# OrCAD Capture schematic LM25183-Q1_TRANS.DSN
size E; title: LM25183-Q1 42-VIN PSR Flyback DC/DC Converter with 65-V,; rev: 1.0; note: Datasheet: SNVSBJ4    EVM: NA; note: Synchronous Step Down Converter
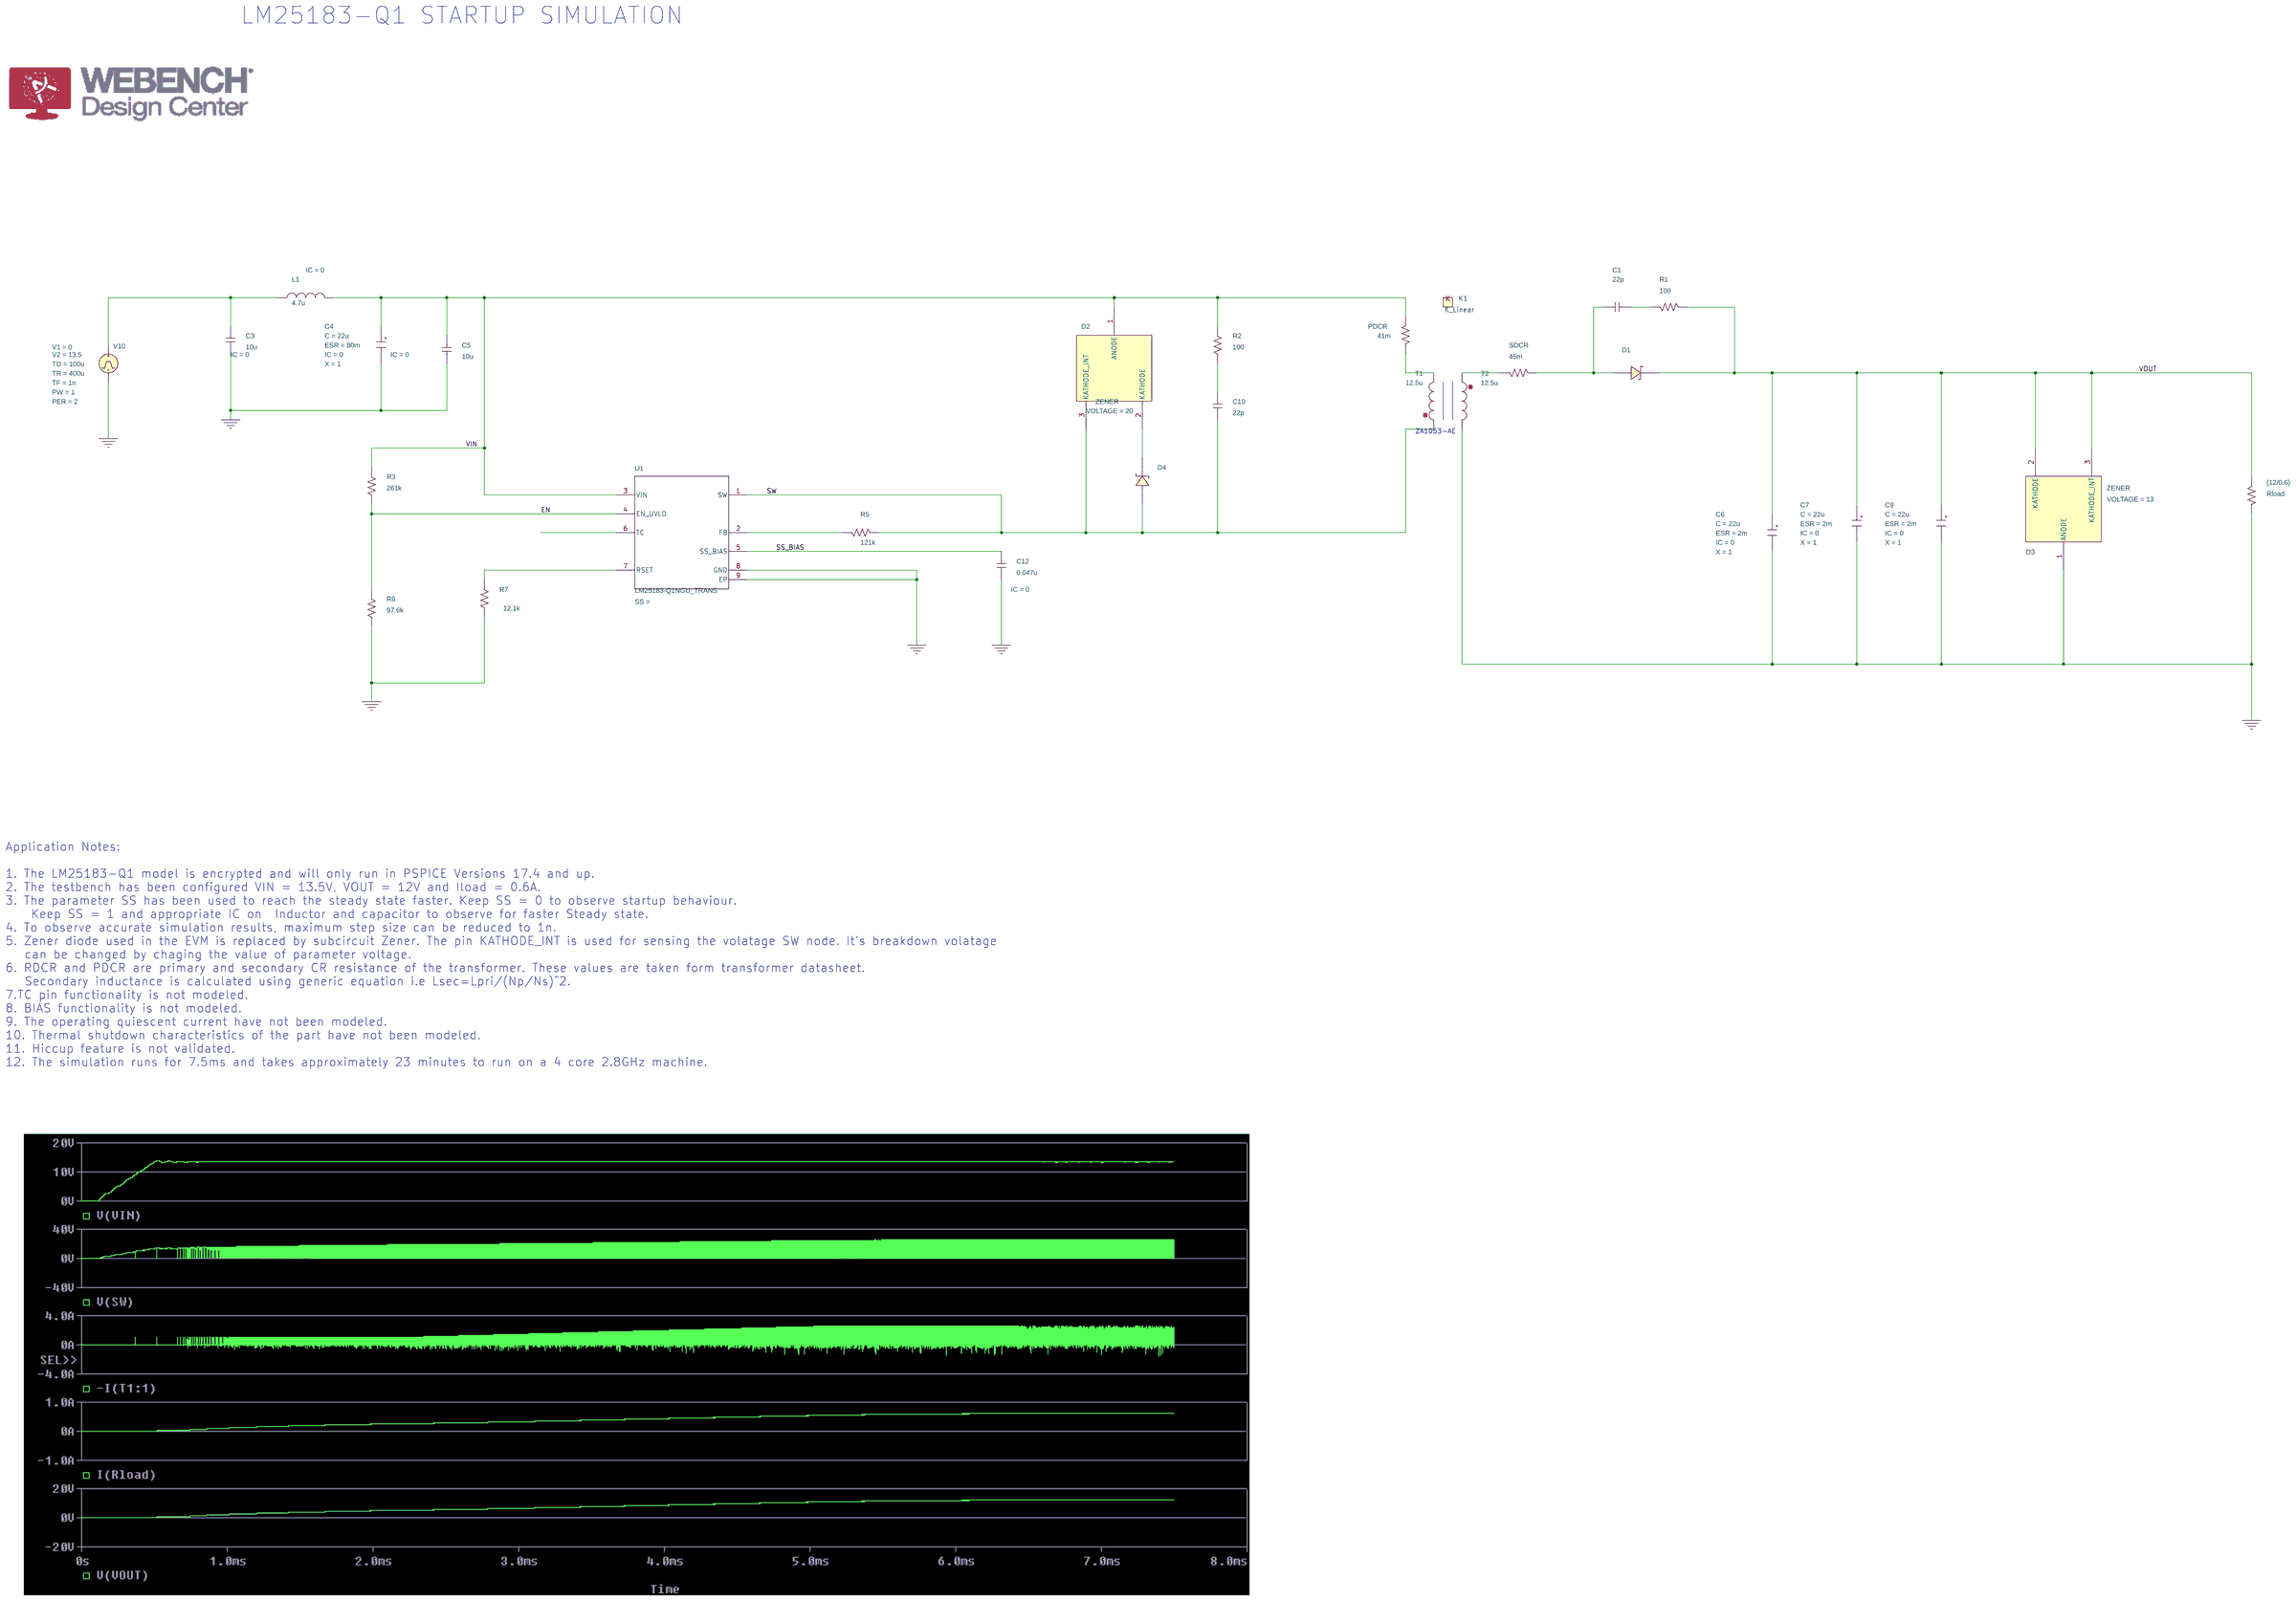
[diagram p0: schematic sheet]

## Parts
C1  22p  [RAD/CK05]
C3  10u  [RAD/CK05]
C4  CESR
C5  10u  [RAD/CK05]
C6  CESR
C7  CESR
C9  CESR
C10  22p  [RAD/CK05]
C12  0.047u  [RAD/CK05]
D1  D_D
D2  ZENER
D3  ZENER
D4  D_D
K1  K_Linear
L1  4.7u  [DISC/.350x.175/LS.200x.100/.034]
PDCR  41m  [AX/RC05]
R1  100  [AX/RC05]
R2  100  [AX/RC05]
R3  261k  [AX/RC05]
R5  121k  [AX/RC05]
R6  97.6k  [AX/RC05]
R7  12.1k  [AX/RC05]
Rload  {12/0.6}  [AX/RC05]
SDCR  45m  [AX/RC05]
T1  12.5u  [DISC/.350x.175/LS.200x.100/.034]
T2  12.5u  [DISC/.350x.175/LS.200x.100/.034]
U1  LM25183-Q1NGU_TRANS  [NGU0008C-IPC_A]
V10  VPULSE

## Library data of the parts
C1 C10 = C
C3 C5 C12 = C: IC: 0
C4 = CESR_0: C: 22u; ESR: 80m; IC: 0; PSpiceTemplate: X^@REFDES %IN %OUT @MODEL PARAMS:  ?C|C=@C||C=100u|  ?ESR|ESR=@ESR||ESR=0.01| ?X|X=@X||X=2|  ?IC|IC=@IC||IC=2|; X: 1
C6 C7 C9 = CESR_0: C: 22u; ESR: 2m; IC: 0; PSpiceTemplate: X^@REFDES %IN %OUT @MODEL PARAMS:  ?C|C=@C||C=100u|  ?ESR|ESR=@ESR||ESR=0.01| ?X|X=@X||X=2|  ?IC|IC=@IC||IC=2|; X: 1
D1 = D_D_2_1: PSpiceTemplate: D^@REFDES %1 %2 @MODEL
D2 = ZENER: VOLTAGE: 20
D3 = ZENER: VOLTAGE: 13
D4 = D_D_2: PSpiceTemplate: D^@REFDES %1 %2 @MODEL
K1 = K_Linear: COUPLING: 1; L1: T1; L2: T2
L1 = L_v2: IC: 0
PDCR R1-R3 R5-R7 Rload SDCR = R
T1 T2 = L
U1 = LM25183-Q1NGU_TRANS
V10 = VPULSE: PER: 2; PW: 1; TD: 100u; TF: 1n; TR: 400u; V1: 0; V2: 13.5

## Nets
VIN: C4.1(IN) C5.1 D2.1(ANODE) L1.2 PDCR.2 R2.1 R3.1 U1.3(VIN)
0: C3.2 C4.3(OUT) C5.2 C6.3(OUT) C7.3(OUT) C9.3(OUT) C12.2 D3.1(ANODE) R6.2 R7.2 Rload.2 T2.2 U1.8(GND) U1.9(EP) V10.2(-)
EN: R3.2 R6.1 U1.4(EN_UVLO)
SS_BIAS: C12.1 U1.5(SS_BIAS)
SW: C10.2 D2.3(KATHODE_INT) D4.1 R5.2 T1.1 U1.1(SW)
VOUT: C6.1(IN) C7.1(IN) C9.1(IN) D1.2 D3.2(KATHODE) D3.3(KATHODE_INT) R1.2 Rload.1
N16770337: C3.1 L1.1 V10.1(+)
N16770435: C10.1 R2.2
N16770603: C1.2 D1.1 SDCR.2
N16770613: C1.1 R1.1
N16777181: R7.1 U1.7(RSET)
N16781197: R5.1 U1.2(FB)
N16799169: D2.2(KATHODE) D4.2
N16804035: PDCR.1 T1.2
N16804051: SDCR.1 T2.1

Not connected (* = marked no-connect by the designer): U1 6(TC)

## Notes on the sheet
- LM25183-Q1 STARTUP SIMULATION
- ZA1053-AE
- Application Notes:
  1. The LM25183-Q1 model is encrypted and will only run in PSPICE Versions 17.4 and up.
  2. The testbench has been configured VIN = 13.5V, VOUT = 12V and Iload = 0.6A.
  3. The parameter SS has been used to reach the steady state faster. Keep SS = 0 to observe startup behaviour.
      Keep SS = 1 and appropriate IC on  Inductor and capacitor to observe for faster Steady state.
  4. To observe accurate simulation results, maximum step size can be reduced to 1n.
  5. Zener diode used in the EVM is replaced by subcircuit Zener. The pin KATHODE_INT is used for sensing the volatage SW node. It's breakdown volatage
     can be changed by chaging the value of parameter voltage.
  6. RDCR and PDCR are primary and secondary CR resistance of the transformer. These values are taken form transformer datasheet.
     Secondary inductance is calculated using generic equation i.e Lsec=Lpri/(Np/Ns)^2.
  7.TC pin functionality is not modeled.
  8. BIAS functionality is not modeled.
  9. The operating quiescent current have not been modeled.
  10. Thermal shutdown characteristics of the part have not been modeled.
  11. Hiccup feature is not validated.
  12. The simulation runs for 7.5ms and takes approximately 23 minutes to run on a 4 core 2.8GHz machine.
